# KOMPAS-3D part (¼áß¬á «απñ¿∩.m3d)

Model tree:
1. Эскиз:1
2. Операция выдавливания:1
     Расстояние 1 = 3.9; Расстояние 2 = 3.2
3. Эскиз:2
4. Операция выдавливания:2
     Расстояние 1 = 2; Расстояние 2 = 3.2
5. Эскиз:3
6. Операция выдавливания:3
     Расстояние 1 = 3.8; Угол 1 = 47; Расстояние 2 = 3.2
7. Эскиз:4
8. Операция выдавливания:4
     Расстояние 1 = 7.9; Расстояние 2 = 3.2
9. Фаска:1
     Угол = 45; Длина 1 = 1; Длина 2 = 1
10. Эскиз:5
11. Отверстие:1
12. Эскиз:7
13. Вырезать элемент выдавливания:2
     Расстояние 2 = 14.8; Расстояние 1 = 14.8
14. Эскиз:8
15. Вырезать элемент выдавливания:3
     Расстояние 1 = 20.8
16. Эскиз:9
17. Операция выдавливания:5
     Расстояние 1 = 15; Расстояние 2 = 7.2
18. Эскиз:10
19. Вырезать элемент выдавливания:4
     Расстояние 1 = 22
20. Эскиз:11
21. Вырезать элемент выдавливания:5
     Расстояние 1 = 2
22. Эскиз:12
23. Операция выдавливания:6
     Расстояние 1 = 3; Расстояние 2 = 7.2
24. Эскиз:13
25. Вырезать элемент выдавливания:6
     Расстояние 2 = 22.1594; Расстояние 1 = 13.7
26. Скругление:1
     Радиус = 1

Referenced files in C:\Program Files\ASCON\KOMPAS-3D V13 Home\Sys\: holelib.lfr
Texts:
  stalker61
  Сплав АЛ8  ГОСТ 1583-93
  Отверстие 01
  (вариант 1)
